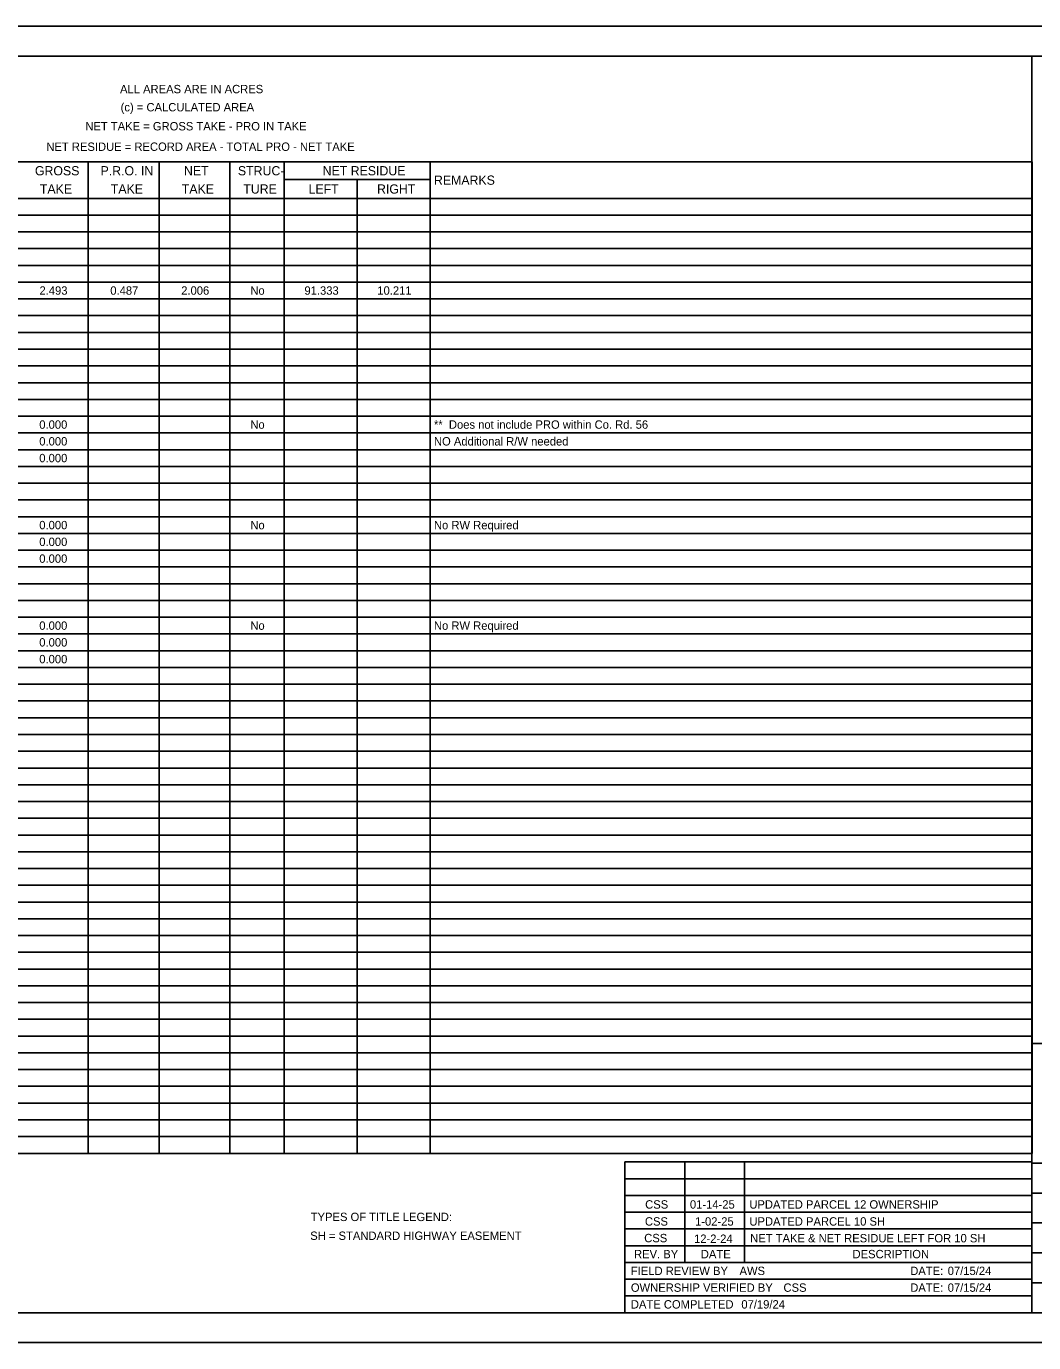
# Model space of a CAD drawing. Extents: x 22.7 to 63.9, y 8.1 to 30.1.
# Drawn here: x 37.85 to 54.69, y 8.06 to 30.06 of the extents above; entities that cross this region are included whole.
import ezdxf

# ---------------------------------------------------------------- set-up
doc = ezdxf.new("R2010")
doc.units = 0
for name, color, linetype in [('Default', 7, 'Continuous'), ('SH_Border', 7, 'Continuous'), ('SH_Cut_Line', 7, 'Continuous'), ('SH_Text', 7, 'Continuous')]:
    doc.layers.add(name, color=color, linetype=linetype)

msp = doc.modelspace()

# ---------------------------------------------------------------- linework, layer by layer
at = {"layer": 'SH_Border'}
for p, q in [((54.659, 8.558), (54.659, 29.558)), ((54.659, 13.058), (56.159, 13.058)), ((54.659, 11.058), (56.159, 11.058)), ((54.659, 10.558), (56.159, 10.558)), ((54.659, 10.058), (56.159, 10.058)), ((54.659, 9.558), (56.159, 9.558)), ((54.659, 9.058), (56.159, 9.058))]:
    msp.add_line(p, q, dxfattribs=at)
msp.add_lwpolyline([(24.159, 29.558), (56.159, 29.558), (56.159, 8.558), (24.159, 8.558)], close=True, dxfattribs=at)
at = {"layer": 'SH_Cut_Line'}
msp.add_lwpolyline([(22.659, 8.058), (56.659, 8.058), (56.659, 30.058), (22.659, 30.058)], close=True, dxfattribs=at)
at = {"layer": 'SH_Text'}
for p, q in [((24.159, 27.792), (54.662, 27.792)), ((38.884, 27.792), (38.884, 11.222)), ((40.07, 27.792), (40.07, 11.222)), ((41.255, 27.792), (41.255, 11.222)), ((42.161, 27.792), (42.161, 11.222)), ((44.599, 27.792), (44.599, 11.222)), ((54.662, 27.792), (54.662, 11.222)), ((42.161, 27.495), (44.599, 27.495)), ((43.38, 27.495), (43.38, 11.222)), ((24.159, 27.182), (54.662, 27.182)), ((24.159, 26.902), (54.662, 26.902)), ((24.159, 26.622), (54.662, 26.622)), ((24.159, 26.342), (54.662, 26.342)), ((24.159, 26.062), (54.662, 26.062)), ((24.159, 25.782), (54.662, 25.782)), ((24.159, 25.502), (54.662, 25.502)), ((24.159, 25.222), (54.662, 25.222)), ((24.159, 24.942), (54.662, 24.942)), ((24.159, 24.662), (54.662, 24.662)), ((24.159, 24.382), (54.662, 24.382)), ((24.159, 24.102), (54.662, 24.102)), ((24.159, 23.822), (54.662, 23.822)), ((24.159, 23.542), (54.662, 23.542)), ((24.159, 23.262), (54.662, 23.262)), ((24.159, 22.982), (54.662, 22.982)), ((24.159, 22.702), (54.662, 22.702)), ((24.159, 22.422), (54.662, 22.422)), ((24.159, 22.142), (54.662, 22.142)), ((24.159, 21.862), (54.662, 21.862)), ((24.159, 21.582), (54.662, 21.582)), ((24.159, 21.302), (54.662, 21.302)), ((24.159, 21.022), (54.662, 21.022)), ((24.159, 20.742), (54.662, 20.742)), ((24.159, 20.462), (54.662, 20.462)), ((24.159, 20.182), (54.662, 20.182)), ((24.159, 19.902), (54.662, 19.902)), ((24.159, 19.622), (54.662, 19.622)), ((24.159, 19.342), (54.662, 19.342)), ((24.159, 19.062), (54.662, 19.062)), ((24.159, 18.782), (54.662, 18.782)), ((24.159, 18.502), (54.662, 18.502)), ((24.159, 18.222), (54.662, 18.222)), ((24.159, 17.942), (54.662, 17.942)), ((24.159, 17.662), (54.662, 17.662)), ((24.159, 17.382), (54.662, 17.382)), ((24.159, 17.102), (54.662, 17.102)), ((24.159, 16.822), (54.662, 16.822)), ((24.159, 16.542), (54.662, 16.542)), ((24.159, 16.262), (54.662, 16.262)), ((24.159, 15.982), (54.662, 15.982)), ((24.159, 15.702), (54.662, 15.702)), ((24.159, 15.422), (54.662, 15.422)), ((24.159, 15.142), (54.662, 15.142)), ((24.159, 14.862), (54.662, 14.862)), ((24.159, 14.582), (54.662, 14.582)), ((24.159, 14.302), (54.662, 14.302)), ((24.159, 14.022), (54.662, 14.022)), ((24.159, 13.742), (54.662, 13.742)), ((24.159, 13.462), (54.662, 13.462)), ((24.159, 13.182), (54.662, 13.182)), ((24.159, 12.902), (54.662, 12.902)), ((24.159, 12.622), (54.662, 12.622)), ((24.159, 12.342), (54.662, 12.342)), ((24.159, 12.062), (54.662, 12.062)), ((24.159, 11.782), (54.662, 11.782)), ((24.159, 11.502), (54.662, 11.502)), ((24.159, 11.222), (54.662, 11.222)), ((47.856, 11.078), (47.856, 8.558)), ((47.856, 11.078), (54.659, 11.078)), ((48.856, 11.078), (48.856, 9.398)), ((49.856, 11.078), (49.856, 9.398)), ((47.856, 10.798), (54.659, 10.798)), ((47.856, 10.518), (54.659, 10.518)), ((47.856, 10.238), (54.659, 10.238)), ((47.856, 9.958), (54.659, 9.958)), ((47.856, 9.678), (54.659, 9.678)), ((47.856, 9.398), (54.659, 9.398)), ((47.856, 9.118), (54.659, 9.118)), ((47.856, 8.838), (54.659, 8.838)), ((54.659, 8.558), (54.659, 8.558))]:
    msp.add_line(p, q, dxfattribs=at)

# ---------------------------------------------------------------- texts
at = {"layer": 'Default'}
for s, p in [('ALL AREAS ARE IN ACRES', (39.418, 28.939)), ('(c) = CALCULATED AREA', (39.428, 28.636)), ('CSS', (48.195, 10.298)), ('01-14-25', (48.943, 10.298)), ('UPDATED PARCEL 12 OWNERSHIP', (49.936, 10.298)), ('CSS', (48.191, 10.014)), ('1-02-25', (49.029, 10.014)), ('UPDATED PARCEL 10 SH', (49.937, 10.014))]:
    msp.add_text(s, height=0.14, dxfattribs=at).set_placement(p)
at = {"layer": 'SH_Text'}
for s, height, p in [('NET TAKE = GROSS TAKE - PRO IN TAKE', 0.14, (38.838, 28.318)), ('NET RESIDUE = RECORD AREA - TOTAL PRO - NET TAKE', 0.14, (38.186, 27.976)), ('GROSS', 0.154, (37.995, 27.567)), ('P.R.O. IN', 0.154, (39.092, 27.567)), ('NET', 0.154, (40.486, 27.567)), ('STRUC-', 0.154, (41.388, 27.567)), ('NET RESIDUE', 0.154, (42.804, 27.567)), ('REMARKS', 0.154, (44.665, 27.41)), ('TAKE', 0.154, (38.078, 27.262)), ('TAKE', 0.154, (39.264, 27.262)), ('TAKE', 0.154, (40.45, 27.262)), ('TURE', 0.154, (41.478, 27.262)), ('LEFT', 0.154, (42.569, 27.262)), ('RIGHT', 0.154, (43.713, 27.262)), ('2.493', 0.14, (38.071, 25.572)), ('0.487', 0.14, (39.255, 25.572)), ('2.006', 0.14, (40.44, 25.572)), ('No', 0.14, (41.596, 25.572)), ('91.333', 0.14, (42.5, 25.572)), ('10.211', 0.14, (43.718, 25.572)), ('0.000', 0.14, (38.068, 23.332)), ('No', 0.14, (41.596, 23.332)), ('**  Does not include PRO within Co. Rd. 56', 0.14, (44.665, 23.332)), ('0.000', 0.14, (38.068, 23.052)), ('NO Additional R/W needed', 0.14, (44.665, 23.052)), ('0.000', 0.14, (38.068, 22.772)), ('0.000', 0.14, (38.068, 21.652)), ('No', 0.14, (41.596, 21.652)), ('No RW Required', 0.14, (44.665, 21.652)), ('0.000', 0.14, (38.068, 21.372)), ('0.000', 0.14, (38.068, 21.092)), ('0.000', 0.14, (38.068, 19.972)), ('No', 0.14, (41.596, 19.972)), ('No RW Required', 0.14, (44.665, 19.972)), ('0.000', 0.14, (38.068, 19.692)), ('0.000', 0.14, (38.068, 19.412)), ('TYPES OF TITLE LEGEND:', 0.14, (42.605, 10.09)), ('SH = STANDARD HIGHWAY EASEMENT', 0.14, (42.597, 9.775)), ('CSS', 0.14, (48.179, 9.736)), ('12-2-24', 0.14, (49.012, 9.725)), ('NET TAKE & NET RESIDUE LEFT FOR 10 SH', 0.14, (49.95, 9.734)), ('REV. BY', 0.14, (48.009, 9.468)), ('DATE', 0.14, (49.125, 9.468)), ('DESCRIPTION', 0.14, (51.661, 9.468)), ('FIELD REVIEW BY', 0.14, (47.956, 9.188)), ('AWS', 0.14, (49.772, 9.188)), ('DATE:', 0.14, (52.626, 9.188)), ('07/15/24', 0.14, (53.252, 9.188)), ('OWNERSHIP VERIFIED BY', 0.14, (47.956, 8.908)), ('CSS', 0.14, (50.507, 8.908)), ('DATE:', 0.14, (52.626, 8.908)), ('07/15/24', 0.14, (53.252, 8.908)), ('DATE COMPLETED', 0.14, (47.956, 8.628)), ('07/19/24', 0.14, (49.803, 8.628))]:
    msp.add_text(s, height=height, dxfattribs=at).set_placement(p)

doc.saveas('drawing.dxf')
